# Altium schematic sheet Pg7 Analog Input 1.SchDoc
size 431 x 279 mm; Date: Not shown in title block; ApprovedBy: Not shown in title block; CheckedBy: Not shown in title block; Author: Not shown in title block; CompanyName: Not shown in title block; Engineer: Not shown in title block; Organization: Not shown in title block; Address1: Not shown in title block; Address2: Not shown in title block; Address3: Not shown in title block; Address4: Not shown in title block; DocumentNumber: 7; Revision: Use project parameter SCH_Rev; SheetNumber: 7; SheetTotal: 9; PageSetup: Record=PageOptions|CenterHorizontal=True|CenterVertical=True|PrintScale=0.64|XCorrection=1.00|YCorrection=1.00|PrintKind=0|BorderSize=5000000|LeftOffset=0|BottomOffset=0|Orientation=2|PaperLength=1000|PaperWidth=1000|Scale=100|PaperSource=15|PrintQuality=600|MediaType=1|DitherType=10|PaperKind=Letter|PrintScaleMode=1
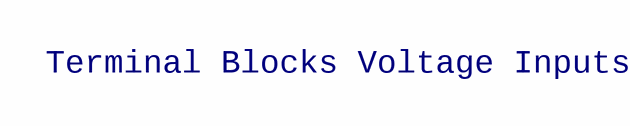
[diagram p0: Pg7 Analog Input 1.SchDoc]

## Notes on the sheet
- Terminal Blocks Voltage Inputs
